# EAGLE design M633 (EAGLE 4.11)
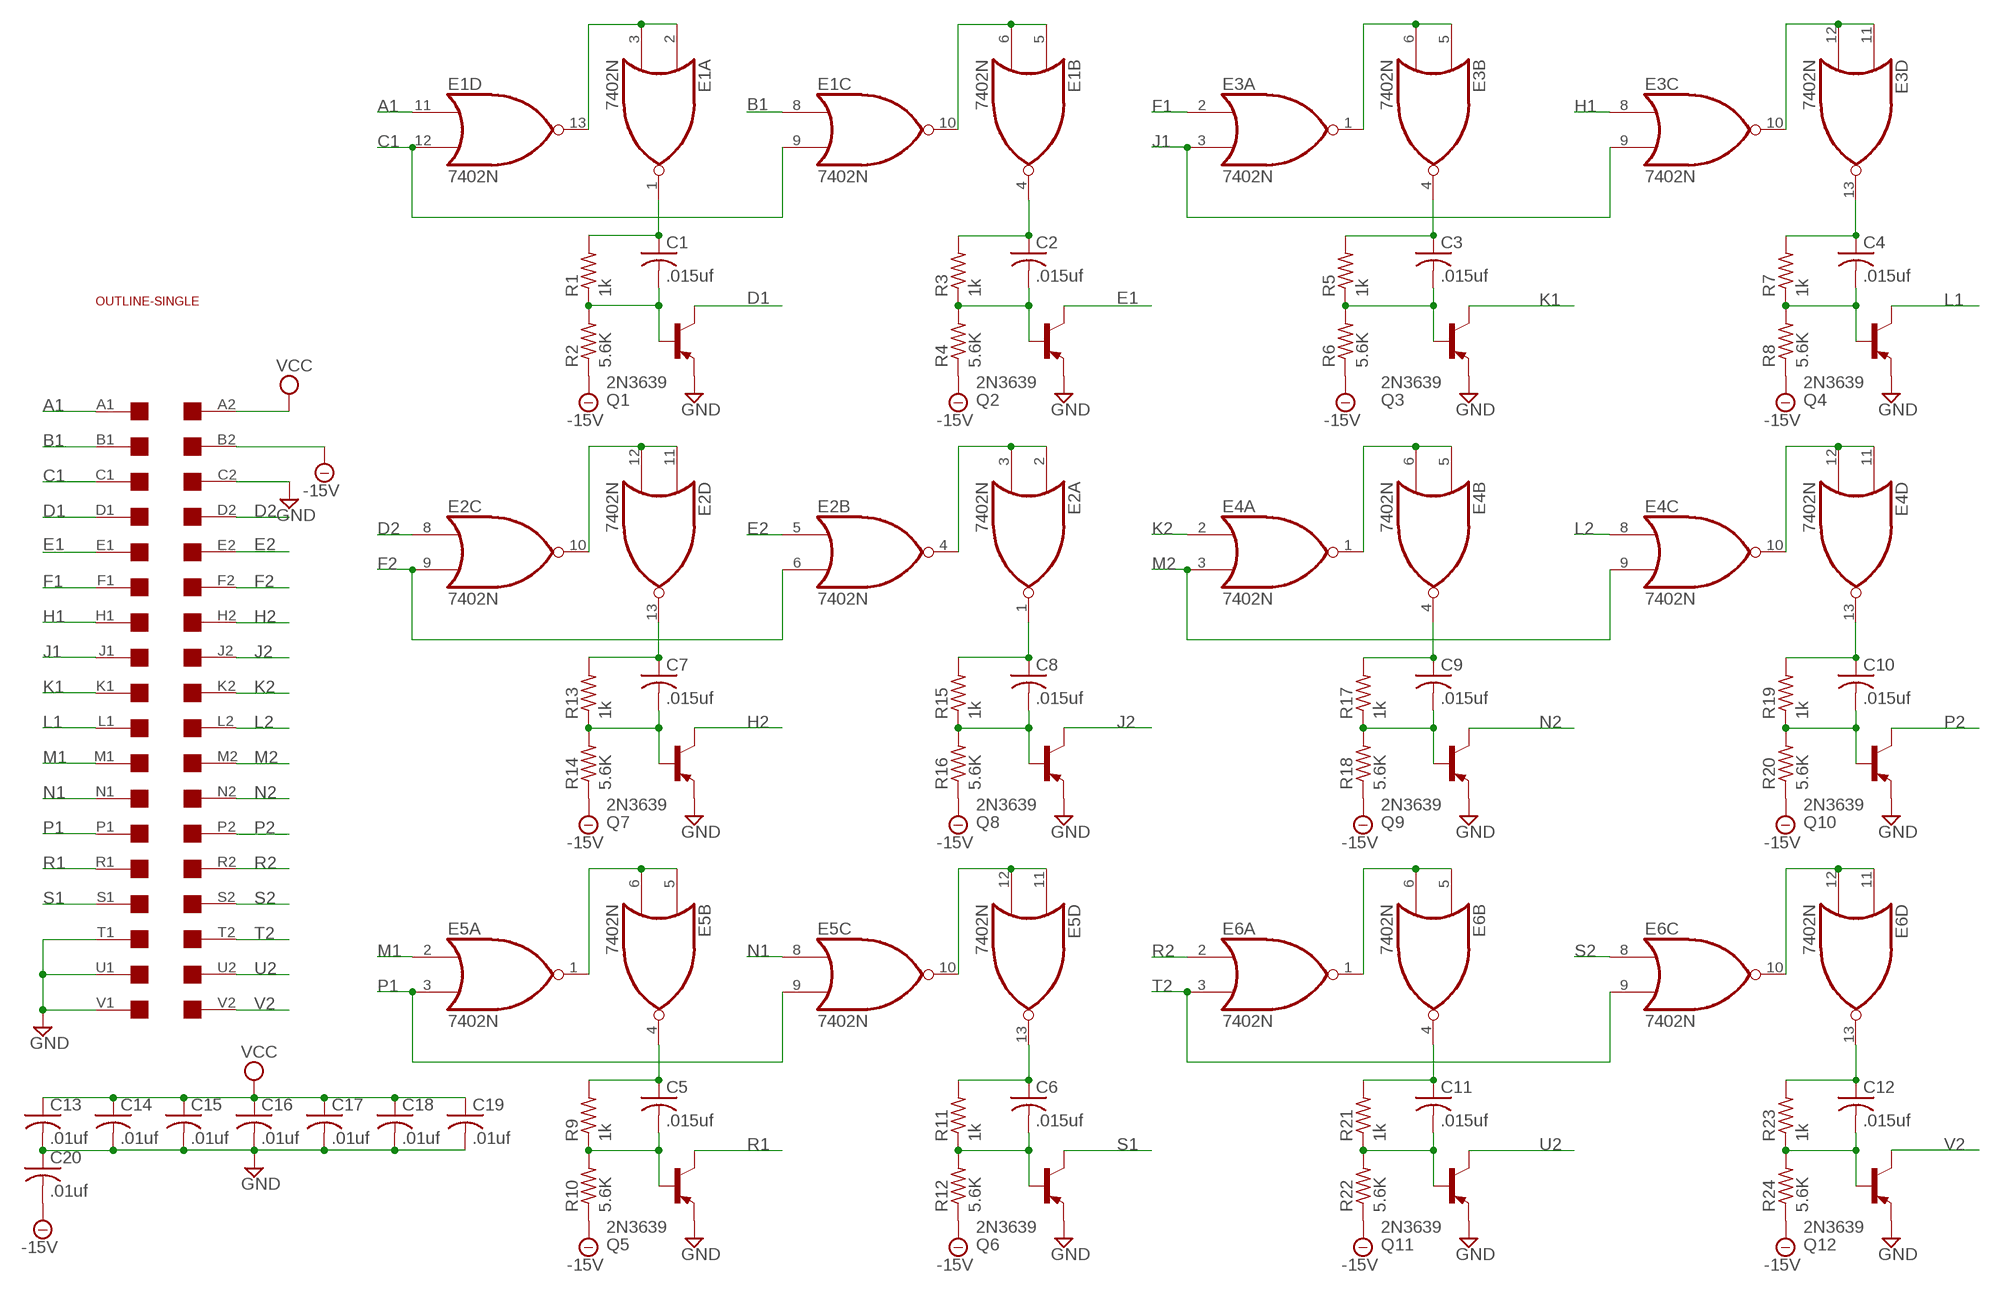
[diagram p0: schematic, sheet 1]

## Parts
C1  .015uf  C-US050-025X075  [C050-025X075]
C2  .015uf  C-US050-025X075  [C050-025X075]
C3  .015uf  C-US050-025X075  [C050-025X075]
C4  .015uf  C-US050-025X075  [C050-025X075]
C5  .015uf  C-US050-025X075  [C050-025X075]
C6  .015uf  C-US050-025X075  [C050-025X075]
C7  .015uf  C-US050-025X075  [C050-025X075]
C8  .015uf  C-US050-025X075  [C050-025X075]
C9  .015uf  C-US050-025X075  [C050-025X075]
C10  .015uf  C-US050-025X075  [C050-025X075]
C11  .015uf  C-US050-025X075  [C050-025X075]
C12  .015uf  C-US050-025X075  [C050-025X075]
C13  .01uf  C-US050-025X075  [C050-025X075]
C14  .01uf  C-US050-025X075  [C050-025X075]
C15  .01uf  C-US050-025X075  [C050-025X075]
C16  .01uf  C-US050-025X075  [C050-025X075]
C17  .01uf  C-US050-025X075  [C050-025X075]
C18  .01uf  C-US050-025X075  [C050-025X075]
C19  .01uf  C-US050-025X075  [C050-025X075]
C20  .01uf  C-US050-025X075  [C050-025X075]
E1  7402N  [DIL14]
E2  7402N  [DIL14]
E3  7402N  [DIL14]
E4  7402N  [DIL14]
E5  7402N  [DIL14]
E6  7402N  [DIL14]
Q1  2N3639  2N5415  [TO39]
Q2  2N3639  2N5415  [TO39]
Q3  2N3639  2N5415  [TO39]
Q4  2N3639  2N5415  [TO39]
Q5  2N3639  2N5415  [TO39]
Q6  2N3639  2N5415  [TO39]
Q7  2N3639  2N5415  [TO39]
Q8  2N3639  2N5415  [TO39]
Q9  2N3639  2N5415  [TO39]
Q10  2N3639  2N5415  [TO39]
Q11  2N3639  2N5415  [TO39]
Q12  2N3639  2N5415  [TO39]
R1  1k  R-US_0207/10  [0207/10]
R2  5.6K  R-US_0207/10  [0207/10]
R3  1k  R-US_0207/10  [0207/10]
R4  5.6K  R-US_0207/10  [0207/10]
R5  1k  R-US_0207/10  [0207/10]
R6  5.6K  R-US_0207/10  [0207/10]
R7  1k  R-US_0207/10  [0207/10]
R8  5.6K  R-US_0207/10  [0207/10]
R9  1k  R-US_0207/10  [0207/10]
R10  5.6K  R-US_0207/10  [0207/10]
R11  1k  R-US_0207/10  [0207/10]
R12  5.6K  R-US_0207/10  [0207/10]
R13  1k  R-US_0207/10  [0207/10]
R14  5.6K  R-US_0207/10  [0207/10]
R15  1k  R-US_0207/10  [0207/10]
R16  5.6K  R-US_0207/10  [0207/10]
R17  1k  R-US_0207/10  [0207/10]
R18  5.6K  R-US_0207/10  [0207/10]
R19  1k  R-US_0207/10  [0207/10]
R20  5.6K  R-US_0207/10  [0207/10]
R21  1k  R-US_0207/10  [0207/10]
R22  5.6K  R-US_0207/10  [0207/10]
R23  1k  R-US_0207/10  [0207/10]
R24  5.6K  R-US_0207/10  [0207/10]
U$1  SINGLE  [EDGE-CON2]
U$2  OUTLINE-SINGLE  [SINGLE]

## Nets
-15V: C20.2 R2.1 R4.1 R6.1 R8.1 R10.1 R12.1 R14.1 R16.1 R18.1 R20.1 R22.1 R24.1 U$1.B2
A1: E1.11(D:I0) U$1.A1
B1: E1.8(C:I0) U$1.B1
C1: E1.9(C:I1) E1.12(D:I1) U$1.C1
D1: Q1.3(C) U$1.D1
D2: E2.8(C:I0) U$1.D2
E1: Q2.3(C) U$1.E1
E2: E2.5(B:I0) U$1.E2
F1: E3.2(A:I0) U$1.F1
F2: E2.6(B:I1) E2.9(C:I1) U$1.F2
GND: C13.2 C14.2 C15.2 C16.2 C17.2 C18.2 C19.2 C20.1 Q1.1(E) Q2.1(E) Q3.1(E) Q4.1(E) Q5.1(E) Q6.1(E) Q7.1(E) Q8.1(E) Q9.1(E) Q10.1(E) Q11.1(E) Q12.1(E) U$1.C2 U$1.T1 U$1.U1 U$1.V1
H1: E3.8(C:I0) U$1.H1
H2: Q7.3(C) U$1.H2
J1: E3.3(A:I1) E3.9(C:I1) U$1.J1
J2: Q8.3(C) U$1.J2
K1: Q3.3(C) U$1.K1
K2: E4.2(A:I0) U$1.K2
L1: Q4.3(C) U$1.L1
L2: E4.8(C:I0) U$1.L2
M1: E5.2(A:I0) U$1.M1
M2: E4.3(A:I1) E4.9(C:I1) U$1.M2
N1: E5.8(C:I0) U$1.N1
N2: Q9.3(C) U$1.N2
N$1: E1.2(A:I0) E1.3(A:I1) E1.13(D:O)
N$2: C1.1 E1.1(A:O) R1.2
N$3: C1.2 Q1.2(B) R1.1 R2.2
N$4: C3.1 E3.4(B:O) R5.2
N$5: C2.1 E1.4(B:O) R3.2
N$6: C2.2 Q2.2(B) R3.1 R4.2
N$7: E1.5(B:I0) E1.6(B:I1) E1.10(C:O)
N$8: E2.10(C:O) E2.11(D:I0) E2.12(D:I1)
N$9: E2.2(A:I0) E2.3(A:I1) E2.4(B:O)
N$10: E4.1(A:O) E4.5(B:I0) E4.6(B:I1)
N$11: E4.10(C:O) E4.11(D:I0) E4.12(D:I1)
N$12: E6.10(C:O) E6.11(D:I0) E6.12(D:I1)
N$13: E6.1(A:O) E6.5(B:I0) E6.6(B:I1)
N$14: E5.10(C:O) E5.11(D:I0) E5.12(D:I1)
N$15: E5.1(A:O) E5.5(B:I0) E5.6(B:I1)
N$16: E3.10(C:O) E3.11(D:I0) E3.12(D:I1)
N$17: E3.1(A:O) E3.5(B:I0) E3.6(B:I1)
N$18: C4.1 E3.13(D:O) R7.2
N$19: C9.1 E4.4(B:O) R17.2
N$20: C10.1 E4.13(D:O) R19.2
N$21: C8.1 E2.1(A:O) R15.2
N$22: C7.1 E2.13(D:O) R13.2
N$23: C7.2 Q7.2(B) R13.1 R14.2
N$24: C8.2 Q8.2(B) R15.1 R16.2
N$25: C9.2 Q9.2(B) R17.1 R18.2
N$26: C10.2 Q10.2(B) R19.1 R20.2
N$27: C5.1 E5.4(B:O) R9.2
N$28: C5.2 Q5.2(B) R9.1 R10.2
N$29: C6.2 Q6.2(B) R11.1 R12.2
N$30: C11.2 Q11.2(B) R21.1 R22.2
N$31: C12.2 Q12.2(B) R23.1 R24.2
N$32: C6.1 E5.13(D:O) R11.2
N$33: C11.1 E6.4(B:O) R21.2
N$34: C12.1 E6.13(D:O) R23.2
N$35: C3.2 Q3.2(B) R5.1 R6.2
N$36: C4.2 Q4.2(B) R7.1 R8.2
P1: E5.3(A:I1) E5.9(C:I1) U$1.P1
P2: Q10.3(C) U$1.P2
R1: Q5.3(C) U$1.R1
R2: E6.2(A:I0) U$1.R2
S1: Q6.3(C) U$1.S1
S2: E6.8(C:I0) U$1.S2
T2: E6.3(A:I1) E6.9(C:I1) U$1.T2
U2: Q11.3(C) U$1.U2
V2: Q12.3(C) U$1.V2
VCC: C13.1 C14.1 C15.1 C16.1 C17.1 C18.1 C19.1 U$1.A2

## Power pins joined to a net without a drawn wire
GND: E1.7(P:GND) E2.7(P:GND) E3.7(P:GND) E4.7(P:GND) E5.7(P:GND) E6.7(P:GND)
VCC: E1.14(P:VCC) E2.14(P:VCC) E3.14(P:VCC) E4.14(P:VCC) E5.14(P:VCC) E6.14(P:VCC)

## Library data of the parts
C1-C20 = rcl:C-US: CAPACITOR, American symbol
E1-E6 = 74xx-us:74*02: Quad 2-input NOR gate
Q1-Q12 = transistor-pnp:2N5415*: PNP Transistror
R1-R24 = rcl:R-US_: RESISTOR, American symbol
U$1 = dec-con:SINGLE: Single-Height DEC board
U$2 = dec-con:OUTLINE-*: Board outlines for DEC boards.

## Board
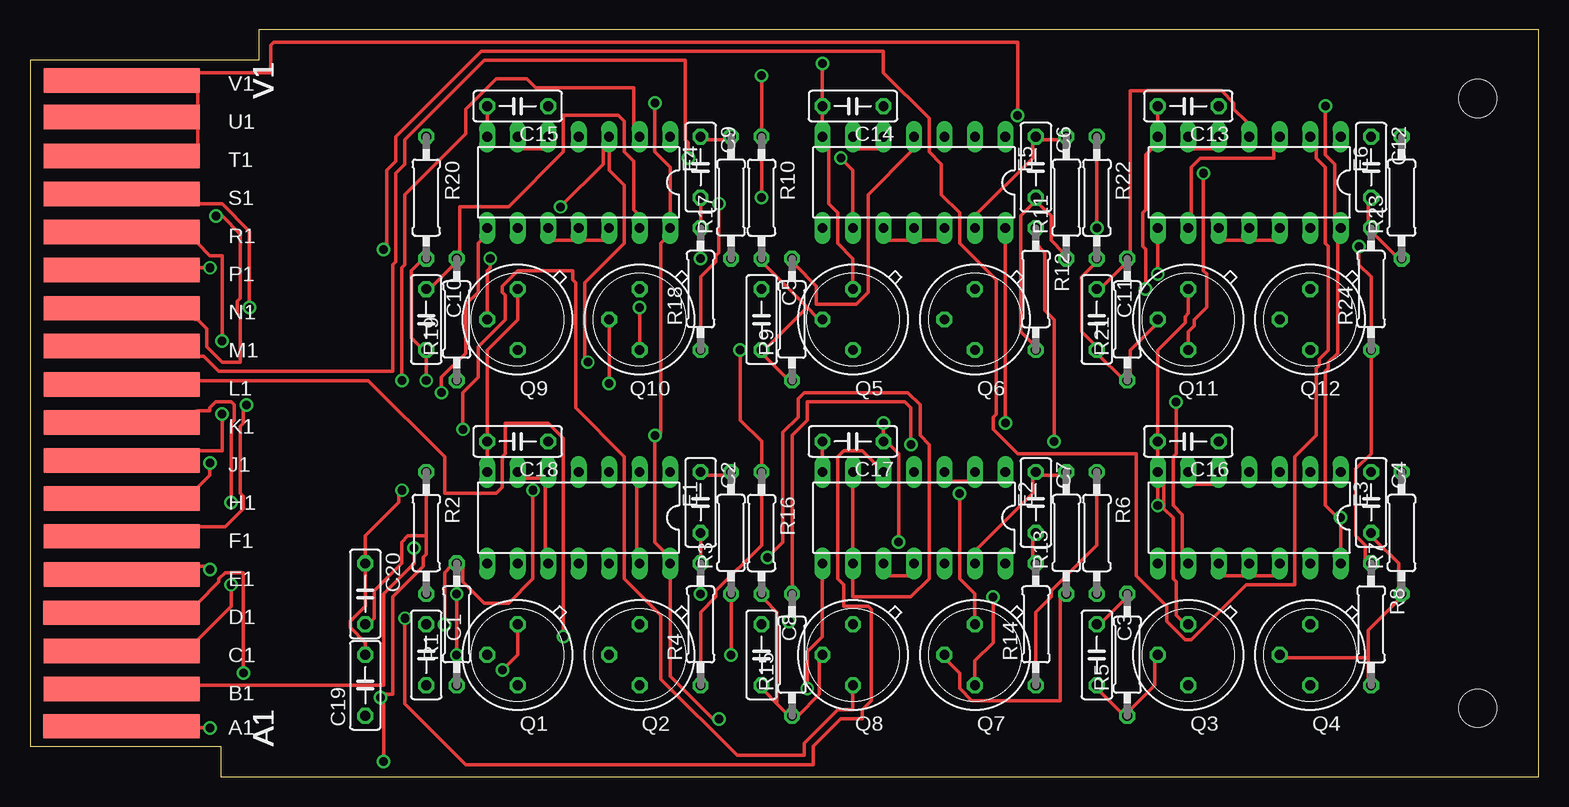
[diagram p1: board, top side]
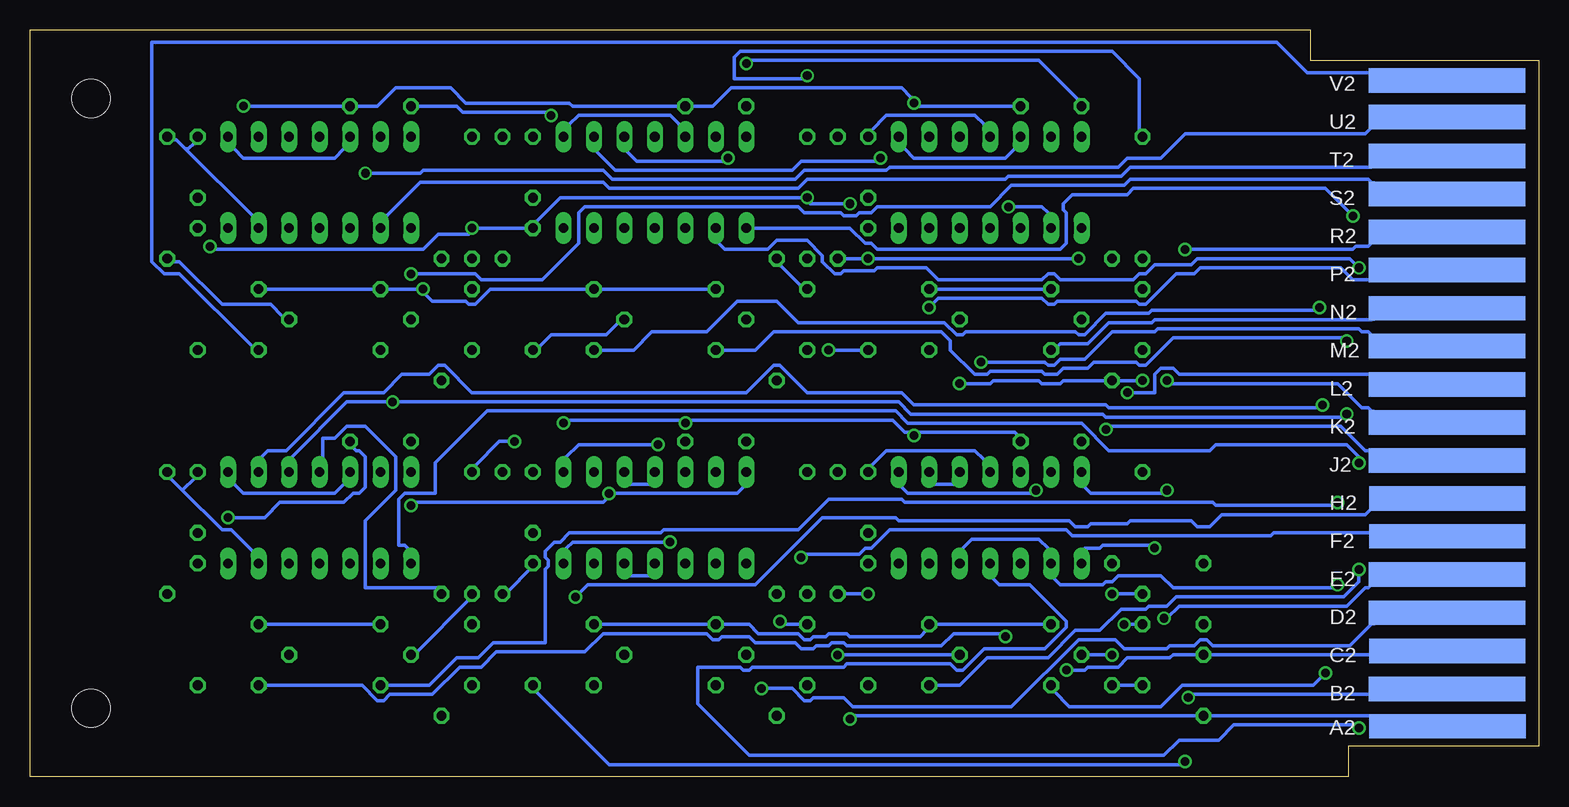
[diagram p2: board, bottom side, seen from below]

Size 125.73 x 62.23 mm. Coordinates in mm from the lower left corner, seen from the top.
Copper layers (1*16): Top 0.035mm / dielectric 1.5mm / Bottom 0.035mm
Design rules "10mils": minimum track width 12mil, minimum drill 28mil, track to track 10mil, track to pad 10mil, pad to pad 10mil, via to via 10mil, smd to smd 10mil, copper to edge 25mil, drill to drill 10mil, minimum pad ring 10mil, minimum via ring 8mil, stop-mask expansion 0mil, vias tented up to drill 0mil, thermal gap 10mil

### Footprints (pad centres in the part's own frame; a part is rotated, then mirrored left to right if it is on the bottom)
C050-025X075 = drill 0.813 octagon: 1 -2.54,0; 2 2.54,0
DIL14 = drill 0.813 long: 1 -7.62,-3.81; 2 -5.08,-3.81; 3 -2.54,-3.81; 4 0,-3.81; 5 2.54,-3.81; 6 5.08,-3.81; 7 7.62,-3.81; 8 7.62,3.81; 9 5.08,3.81; 10 2.54,3.81; 11 0,3.81; 12 -2.54,3.81; 13 -5.08,3.81; 14 -7.62,3.81
TO39 = drill 0.813 octagon: 1 0,-2.54; 2 2.54,0; 3 0,2.54
0207/10 = drill 0.813 octagon: 1 -5.08,0; 2 5.08,0
EDGE-CON2 = smd 13.017 x 2.032: A1 7.633,4.207; B1 7.639,7.327; C1 7.636,10.489; D1 7.633,13.665; E1 7.642,16.84; F1 7.642,20.041; H1 7.642,23.19; J1 7.642,26.34; K1 7.642,29.515; L1 7.642,32.69; M1 7.642,35.89; N1 7.642,39.04; P1 7.642,42.24; R1 7.642,45.39; S1 7.642,48.565; T1 7.642,51.74; U1 7.642,54.966; V1 7.642,58.026 | smd 13.017 x 2.032 bottom: A2 7.614,4.207; B2 7.642,7.328; C2 7.617,10.49; D2 7.642,13.665; E2 7.642,16.84; F2 7.617,20.041; H2 7.617,23.19; J2 7.642,26.34; K2 7.642,29.515; L2 7.642,32.69; M2 7.642,35.89; N2 7.642,39.04; P2 7.642,42.24; R2 7.642,45.39; S2 7.642,48.565; T2 7.642,51.74; U2 7.642,54.966; V2 7.642,58.026
SINGLE = hole 3.175: 120.65,56.515; 120.65,5.715

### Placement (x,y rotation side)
C1  33.02,10.16 270 top
C2  55.88,22.86 270 top
C3  88.9,10.16 270 top
C4  111.76,22.86 270 top
C5  60.96,38.1 270 top
C6  83.82,50.8 270 top
C7  83.82,22.86 270 top
C8  60.96,10.16 270 top
C9  55.88,50.8 270 top
C10  33.02,38.1 270 top
C11  88.9,38.1 270 top
C12  111.76,50.8 270 top
C13  96.52,55.88 180 top
C14  68.58,55.88 180 top
C15  40.64,55.88 180 top
C16  96.52,27.94 180 top
C17  68.58,27.94 180 top
C18  40.64,27.94 180 top
C19  27.94,7.62 90 top
C20  27.94,15.24 270 top
E1  45.72,21.59 180 top
E2  73.66,21.59 180 top
E3  101.6,21.59 180 top
E4  45.72,49.53 180 top
E5  73.66,49.53 180 top
E6  101.6,49.53 180 top
Q1  40.64,10.16 180 top
Q2  50.8,10.16 180 top
Q3  96.52,10.16 180 top
Q4  106.68,10.16 180 top
Q5  68.58,38.1 180 top
Q6  78.74,38.1 180 top
Q7  78.74,10.16 180 top
Q8  68.58,10.16 180 top
Q9  40.64,38.1 180 top
Q10  50.8,38.1 180 top
Q11  96.52,38.1 180 top
Q12  106.68,38.1 180 top
R1  35.56,12.7 90 top
R2  33.02,20.32 270 top
R3  58.42,20.32 90 top
R4  55.88,12.7 90 top
R5  91.44,10.16 90 top
R6  88.9,20.32 270 top
R7  114.3,20.32 90 top
R8  111.76,12.7 270 top
R9  63.5,38.1 90 top
R10  60.96,48.26 270 top
R11  86.36,48.26 90 top
R12  83.82,40.64 270 top
R13  86.36,20.32 90 top
R14  83.82,12.7 90 top
R15  63.5,10.16 90 top
R16  60.96,20.32 270 top
R17  58.42,48.26 90 top
R18  55.88,40.64 90 top
R19  35.56,38.1 90 top
R20  33.02,48.26 270 top
R21  91.44,38.1 90 top
R22  88.9,48.26 270 top
R23  114.3,48.26 90 top
R24  111.76,40.64 90 top
U$1  0,0 0 top
U$2  0,0 0 top

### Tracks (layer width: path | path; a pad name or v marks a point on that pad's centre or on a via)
-15V  (via drill 0.71)
  Top 0.305: 33.02,20.07 33.02,24.89 R2.1 | 33.02,20.07 33.02,18.54 32.77,18.29 32.77,17.53 30.23,14.99 30.23,6.86 29.46,6.86 v29.21,6.6 29.46,6.1 v29.46,1.27 | 33.02,20.07 31.5,20.07 30.99,19.56 30.99,17.78 28.7,15.49 28.7,13.21 28.45,12.95 C20.2 | R4.1 55.88,8.13 55.88,13.72 57.15,14.99 57.15,15.49 60.96,19.3 60.96,24.89 R16.1 60.96,25.91 60.96,27.94 59.18,29.72 v59.18,35.56 | R14.1 83.82,8.13 83.82,13.72 85.09,14.99 85.09,15.49 88.9,19.3 88.9,24.89 R6.1 | R8.1 111.25,18.03 111.25,19.3 110.49,20.07 110.49,25.65 111.76,26.92 111.76,35.05 R24.1 111.76,36.07 111.76,41.66 110.74,42.67 v110.74,44.2 | v88.9,45.72 88.9,52.83 R22.1 | v60.96,58.42 60.96,53.85 R10.1 60.96,52.83 v60.96,48.26 | v85.34,27.94 85.34,38.1 84.58,38.86 84.58,43.69 83.82,44.45 83.82,45.21 R12.1 | v57.4,47.75 57.4,43.69 57.15,43.43 57.15,42.93 55.88,41.66 55.88,36.07 R18.1
  Bottom 0.305: v29.21,6.6 28.96,6.86 13.97,6.86 U$1.B2 | v59.18,35.56 56.39,35.56 R18.1 | v60.96,58.42 61.21,58.17 67.06,58.17 67.06,59.94 66.55,60.45 35.56,60.45 33.27,58.17 33.27,53.85 R20.1 | v110.74,44.2 110.49,43.94 92.96,43.94 91.69,45.21 89.15,45.21 v88.9,45.72 84.33,45.72 R12.1 83.57,46.23 81.53,48.26 v60.96,48.26 60.71,47.75 v57.4,47.75 | v85.34,27.94 86.61,27.94 88.65,25.91 R6.1 | v29.46,1.27 29.72,1.02 77.47,1.02 83.57,7.11 R14.1
A1  (via drill 0.71)
  Top 0.305: v14.99,4.06 13.97,4.06 U$1.A1
  Bottom 0.305: v14.99,4.06 15.24,4.32 25.4,4.32 26.67,3.05 29.97,3.05 31.24,1.78 65.79,1.78 70.1,6.1 70.1,9.14 66.55,9.14 66.29,8.89 65.79,8.89 65.53,9.14 57.91,9.14 57.66,9.4 49.02,9.4 48.51,8.89 48.01,8.89 46.23,10.67 41.15,10.67 39.37,12.45 39.37,12.95 42.42,16 44.96,16 45.47,16.51 E1.11
B1  (via drill 0.71)
  Top 0.305: v32,19.05 32,17.78 29.46,15.24 29.46,7.62 13.97,7.62 U$1.B1
  Bottom 0.305: v32,19.05 32.26,19.3 36.32,19.3 36.58,19.05 37.85,19.05 E1.8
C1  (via drill 0.71)
  Top 0.305: v16.76,16 16.76,14.22 13.97,11.43 U$1.C1
  Bottom 0.305: v16.76,16 17.02,15.75 30.48,15.75 31.5,16.76 35.05,16.76 35.56,16.26 36.07,16.26 36.32,16 39.88,16 40.39,16.51 E1.9 40.89,19.05 41.66,19.81 47.24,19.81 48.01,19.05 E1.12
D1  (via drill 0.71)
  Top 0.305: v17.78,8.64 17.78,17.02 16.26,17.02 15.75,16.51 15.75,16.26 13.97,14.48 U$1.D1
  Bottom 0.305: v17.78,8.64 18.8,7.62 29.72,7.62 31.5,5.84 39.12,5.84 40.39,7.11 Q1.3
D2  (via drill 0.71)
  Top 0.305: v64.77,7.37 64.77,10.41 66.04,11.68 66.04,16.51 E2.8
  Bottom 0.305: v64.77,7.37 62.23,7.37 61.21,6.35 60.71,6.35 60.45,6.6 57.91,6.6 57.15,5.84 43.94,5.84 38.35,11.43 35.31,11.43 34.54,10.67 30.99,10.67 30.73,10.92 28.7,10.92 28.19,11.43 27.69,11.43 27.18,10.92 15.75,10.92 13.97,12.7 U$1.D2
E1  (via drill 0.71)
  Top 0.305: v14.99,17.27 14.99,17.53 13.97,17.53 U$1.E1
  Bottom 0.305: v14.99,17.27 14.99,16.26 16.26,14.99 30.23,14.99 30.99,14.22 32.51,14.22 32.77,13.97 34.8,13.97 36.58,12.19 38.61,12.19 40.89,9.91 45.97,9.91 48.26,7.62 50.29,7.62 Q2.3
E2  (via drill 0.71)
  Top 0.305: v31.24,13.21 31.24,6.1 36.32,1.02 65.28,1.02 65.28,2.54 67.56,4.83 69.34,4.83 69.34,5.59 70.1,6.35 70.1,13.97 69.85,14.22 67.82,14.22 67.82,16 67.31,16.51 67.31,26.67 67.82,27.18 69.34,27.18 70.61,25.91 E2.5
  Bottom 0.305: v31.24,13.21 30.99,13.21 29.97,14.22 16,14.22 14.48,15.75 14.22,15.75 13.97,16 U$1.E2
F1  (via drill 0.71)
  Top 0.305: v18.03,30.99 17.78,30.73 17.78,29.46 17.53,29.21 17.53,23.62 17.78,23.37 17.78,22.35 16.26,20.83 13.97,20.83 U$1.F1
  Bottom 0.305: v18.03,30.99 18.29,30.73 35.81,30.73 36.07,30.99 52.07,30.99 53.09,32 60.96,32 63.25,34.29 63.75,34.29 66.04,32 88.9,32 91.19,34.29 91.69,34.29 92.46,33.53 94.74,33.53 96.27,32 99.57,32 104.39,27.18 105.92,27.18 106.43,26.67 E3.2
F2  (via drill 0.71)
  Top 0.305: v61.47,18.29 62.74,19.56 62.74,28.7 64.01,29.97 64.01,31.5 64.52,32 73.15,32 74.17,30.99 74.17,28.45 74.93,27.69 74.93,16.51 73.41,14.99 68.58,14.99 68.58,16.51 E2.9 68.58,19.05 68.58,24.13 E2.6
  Bottom 0.305: v61.47,18.29 61.21,18.54 56.64,18.54 56.13,19.05 55.63,19.05 54.1,20.57 39.37,20.57 38.86,20.07 22.35,20.07 22.1,20.32 13.97,20.32 U$1.F2
GND  (via drill 0.71)
  Top 0.305: E1.7 38.1,26.67 38.1,27.43 C18.2 38.1,28.45 38.1,35.56 40.64,38.1 40.64,40.13 Q9.1 | C19.2 27.94,10.67 27.94,11.18 26.67,12.45 26.67,12.95 27.94,14.22 27.94,17.27 C20.1 27.94,18.29 27.94,20.07 30.73,22.86 30.73,23.62 v30.99,23.88 | E2.7 66.04,26.67 66.04,27.43 C17.2 | v77.47,23.62 77.47,16.51 78.74,15.24 78.74,13.21 Q7.1 | U$1.T1 13.97,52.58 13.97,54.1 U$1.U1 13.97,55.88 13.97,57.15 U$1.V1 13.97,58.67 20.07,58.67 20.07,60.96 20.32,61.21 82.3,61.21 v82.3,55.12 | E4.7 38.1,54.61 38.1,55.37 C15.2 | v66.04,59.44 66.04,56.39 C14.2 66.04,55.37 66.04,54.61 E5.7 66.55,52.32 66.55,47.75 67.31,46.99 67.31,44.45 68.58,43.18 68.58,41.15 Q5.1 | C13.2 93.98,55.37 93.98,54.61 E6.7 93.47,52.32 92.96,51.82 92.96,47.24 92.71,46.99 92.71,44.2 92.96,43.94 v92.96,40.64 | E3.7 93.98,26.67 93.98,27.43 C16.2 93.98,28.45 93.98,35.56 96.27,37.85 96.27,38.35 96.52,38.61 96.52,40.13 Q11.1 | Q3.1 96.01,12.95 95.5,13.46 95.5,16.26 95.25,16.51 95.25,21.59 94.49,22.35 94.49,24.38 E3.7 | v93.98,22.61 93.98,24.13 E3.7 | v39.37,8.89 40.64,10.16 40.64,12.19 Q1.1
  Bottom 0.305: Q9.1 41.15,40.64 50.29,40.64 Q10.1 | U$1.C2 13.97,10.16 27.43,10.16 C19.2 28.45,10.16 30.48,10.16 30.73,9.91 34.29,9.91 35.05,9.14 37.59,9.14 37.85,8.89 v39.37,8.89 | v30.99,23.88 31.24,23.62 37.34,23.62 37.85,24.13 E1.7 | Q1.1 41.15,12.7 50.29,12.7 Q2.1 51.05,12.19 51.56,11.68 57.4,11.68 57.66,11.94 59.18,11.94 59.44,11.68 60.45,11.68 60.71,11.43 61.21,11.43 61.72,11.94 65.02,11.94 65.79,12.7 68.07,12.7 Q8.1 69.09,12.7 78.23,12.7 Q7.1 | E2.7 66.29,24.13 66.8,23.62 v77.47,23.62 77.72,23.11 77.98,22.86 93.73,22.86 v93.98,22.61 | v66.04,59.44 65.79,59.69 41.66,59.69 38.35,56.39 C15.2 | Q5.1 69.09,40.64 78.23,40.64 Q6.1 79.25,40.64 87.38,40.64 88.65,39.37 89.15,39.37 89.41,39.62 92.2,39.62 92.71,40.13 v92.96,40.64 96.01,40.64 Q11.1 97.03,40.64 106.17,40.64 Q12.1 | Q3.1 97.03,12.7 106.17,12.7 Q4.1 | v82.3,55.12 82.55,55.37 89.66,55.37 90.17,55.88 93.47,55.88 C13.2
H1  (via drill 0.71)
  Top 0.305: v14.99,26.16 14.99,25.15 13.97,24.13 U$1.H1
  Bottom 0.305: v14.99,26.16 14.99,26.67 16,27.69 26.92,27.69 27.43,27.18 35.81,27.18 38.1,29.46 52.58,29.46 53.59,30.48 87.63,30.48 91.95,26.16 91.95,23.62 94.49,23.62 95,23.11 95,19.3 94.49,19.3 94.23,19.05 E3.8
H2  (via drill 0.71)
  Top 0.305: v80.26,14.99 80.26,11.18 78.74,9.65 78.74,8.13 Q7.3
  Bottom 0.305: v80.26,14.99 79.25,16 65.28,16 59.69,21.59 53.59,21.59 53.34,21.34 39.12,21.34 38.61,20.83 37.59,20.83 37.34,21.08 34.29,21.08 34.04,21.34 28.96,21.34 28.45,20.83 27.43,20.83 26.42,21.84 14.48,21.84 13.97,22.35 U$1.H2
J1  (via drill 0.71)
  Top 0.305: v16,30.23 16,27.18 13.97,27.18 U$1.J1 | v95.5,31.24 95.5,26.92 95.25,26.67 95.25,22.61 96.01,21.84 96.01,18.8 E3.9
  Bottom 0.305: v16,30.23 16.26,29.97 36.07,29.97 36.32,30.23 52.32,30.23 53.34,31.24 v95.5,31.24 99.31,31.24 103.89,26.67 E3.3
J2  (via drill 0.71)
  Top 0.305: v36.07,28.96 36.07,32 37.34,33.27 37.34,35.81 39.62,38.1 39.62,40.13 39.37,40.39 39.37,40.89 40.64,42.16 45.21,42.16 45.21,41.4 45.47,41.15 45.47,30.73 49.53,26.67 49.53,16.51 52.58,13.46 52.58,8.13 58.93,1.78 64.52,1.78 64.52,2.79 67.31,5.59 68.58,5.59 68.58,7.11 Q8.3
  Bottom 0.305: v36.07,28.96 35.81,29.21 16.51,29.21 14.48,27.18 13.97,27.18 U$1.J2
K1  (via drill 0.71)
  Top 0.305: v16.76,22.86 16.76,29.46 17.02,29.72 17.02,30.99 16.76,31.24 15.49,31.24 14.99,30.73 14.99,30.48 13.97,30.48 U$1.K1
  Bottom 0.305: v16.76,22.86 17.02,22.61 26.92,22.61 27.18,22.86 52.83,22.86 53.09,23.11 59.18,23.11 61.72,20.57 72.9,20.57 73.15,20.32 80.77,20.32 81.53,19.56 82.04,19.56 82.8,18.8 82.8,18.29 82.55,18.03 82.55,17.53 82.8,17.27 82.8,11.18 87.12,11.18 88.39,9.91 90.17,9.91 92.46,7.62 96.01,7.62 Q3.3
K2  (via drill 0.71)
  Top 0.305: v30.99,33.02 30.99,42.42 31.24,42.67 31.24,48.51 36.32,53.59 36.32,55.63 38.86,58.17 41.4,58.17 42.16,57.4 50.29,57.4 50.29,54.36 E4.2
  Bottom 0.305: v30.99,33.02 30.73,32.77 16.76,32.77 14.73,30.73 14.22,30.73 13.97,30.48 U$1.K2
L1  (via drill 0.71)
  Top 0.305: v44.45,11.68 44.45,28.19 43.18,29.46 39.62,29.46 39.62,26.92 39.37,26.67 39.37,24.13 38.86,23.62 34.54,23.62 34.54,26.67 28.19,33.02 13.97,33.02 U$1.L1
  Bottom 0.305: v44.45,11.68 44.7,11.94 48.77,11.94 49.78,10.92 57.66,10.92 57.91,11.18 58.93,11.18 59.18,10.92 60.2,10.92 60.45,10.67 61.47,10.67 61.98,11.18 65.28,11.18 65.79,11.68 68.07,11.68 68.33,11.43 68.83,11.43 69.34,11.94 77.98,11.94 79.5,10.41 86.87,10.41 88.14,9.14 89.92,9.14 92.2,6.86 95.76,6.86 96.27,6.35 96.77,6.35 98.04,7.62 106.17,7.62 Q4.3
L2  (via drill 0.71)
  Top 0.305: v34.29,32 34.29,33.27 36.32,35.31 36.32,39.37 37.34,40.39 37.34,44.45 37.59,44.7 E4.8
  Bottom 0.305: v34.29,32 32,32 32,33.53 31.5,34.04 30.48,34.04 29.97,33.53 13.97,33.53 U$1.L2
M1  (via drill 0.71)
  Top 0.305: v54.86,51.56 54.86,52.83 54.61,53.09 54.61,59.69 37.85,59.69 31.24,53.09 31.24,51.05 30.48,50.29 30.48,42.93 30.23,42.67 30.23,33.78 15.75,33.78 14.48,35.05 13.97,35.05 U$1.M1
  Bottom 0.305: v54.86,51.56 55.12,51.31 61.47,51.31 62.23,50.55 76.96,50.55 78.49,52.07 E5.2
M2  (via drill 0.71)
  Top 0.305: v46.48,34.54 46.23,34.8 46.23,41.15 49.53,44.45 49.53,49.28 48.26,50.55 48.26,52.07 E4.3 47.75,52.32 47.75,51.05 v44.2,47.5
  Bottom 0.305: v46.48,34.54 41.15,34.54 40.89,34.29 40.39,34.29 39.88,34.8 37.85,34.8 35.56,37.08 32,37.08 31.75,37.34 14.99,37.34 14.73,37.08 14.22,37.08 13.97,36.83 U$1.M2 | v44.2,47.5 41.4,47.5 40.89,46.99 E4.9
N1  (via drill 0.71)
  Top 0.305: v15.49,46.74 16,46.74 17.53,45.21 17.53,39.88 17.27,39.62 17.27,38.61 17.53,38.35 17.53,34.54 16,34.54 14.73,35.81 14.73,37.34 13.97,38.1 U$1.N1
  Bottom 0.305: v15.49,46.74 17.78,49.02 33.78,49.02 34.29,48.51 38.86,48.51 39.62,47.75 39.62,47.24 39.37,46.99 39.37,44.45 39.88,43.94 55.12,43.94 55.63,44.45 56.13,44.45 57.4,45.72 65.53,45.72 E5.8
N2
  Bottom 0.305: Q9.3 40.13,35.81 39.88,36.07 37.59,36.07 35.81,37.85 32.26,37.85 32,38.1 13.97,38.1 U$1.N2
N$1
  Top 0.305: E1.13 50.55,19.05 50.55,24.13 E1.2
  Bottom 0.305: E1.3 48.77,24.38 50.29,24.38 E1.2
N$2  (via drill 0.71)
  Top 0.305: v34.54,12.7 34.54,17.02 35.05,17.53 R1.2 36.07,17.53 36.07,16.26 37.85,14.48 39.88,14.48 41.91,16.51 v41.91,23.88
  Bottom 0.305: v34.54,12.7 33.53,12.7 C1.1 | v41.91,23.88 42.16,23.62 52.58,23.62 53.09,24.13 E1.1
N$3  (via drill 0.71)
  Top 0.305: v35.56,15.24 v35.56,10.16 35.56,8.13 R1.1
  Bottom 0.305: C1.2 33.53,7.62 35.05,7.62 R1.1 | v35.56,15.24 33.53,15.24 R2.2 | v35.56,10.16 37.59,10.16 Q1.2
N$4
  Top 0.305: C3.1 89.41,12.95 91.19,14.73 R5.2
  Bottom 0.305: E3.4 101.35,26.67 101.35,28.19 100.33,28.19 99.31,29.21 97.79,29.21 95.25,26.67 95.25,23.88 97.79,21.34 97.79,15.75 91.69,15.75 R5.2
N$5
  Top 0.305: R3.2 57.91,25.15 56.39,25.15 C2.1
  Bottom 0.305: E1.4 46.23,26.42 46.99,27.18 54.36,27.18 55.63,25.91 C2.1
N$6  (via drill 0.71)
  Top 0.305: C2.2 55.88,19.81 55.88,18.29 R4.2 55.88,17.27 v55.88,15.24 | v58.42,10.16 58.42,14.73 R3.1
  Bottom 0.305: v58.42,10.16 48.77,10.16 Q2.2 | v55.88,15.24 57.91,15.24 R3.1
N$7
  Top 0.305: E1.6 41.15,24.89 42.67,24.89 E1.5 42.93,24.13 42.93,19.05 E1.10
N$8
  Top 0.305: E2.10 71.63,16.76 73.15,16.76 E2.11
  Bottom 0.305: E2.12 75.69,16.76 74.17,16.76 E2.11
N$9
  Top 0.305: E2.2 78.23,24.64 76.71,24.64 E2.3
  Bottom 0.305: E2.4 74.17,24.38 75.69,24.38 E2.3
N$10
  Top 0.305: E4.6 41.15,52.32 42.67,52.32 E4.5
  Bottom 0.305: E4.1 52.83,52.32 52.07,51.56 44.45,51.56 43.69,52.32 E4.5
N$11
  Top 0.305: E4.10 43.69,44.7 45.21,44.7 E4.11 46.23,44.7 47.75,44.7 E4.12
N$12
  Top 0.305: E6.10 99.57,44.7 101.09,44.7 E6.11 102.11,44.7 103.63,44.7 E6.12
N$13
  Top 0.305: E6.6 97.03,52.32 98.55,52.32 E6.5
  Bottom 0.305: E6.1 108.71,52.32 107.95,51.56 100.33,51.56 99.57,52.32 E6.5
N$14
  Top 0.305: E5.10 71.63,44.7 73.15,44.7 E5.11 74.17,44.7 75.69,44.7 E5.12
N$15
  Top 0.305: E5.6 69.09,52.32 70.61,52.32 E5.5
  Bottom 0.305: E5.1 80.77,54.36 80.01,55.12 72.39,55.12 71.63,54.36 E5.5
N$16
  Top 0.305: E3.10 99.57,16.76 101.09,16.76 E3.11 102.11,16.76 103.63,16.76 E3.12
N$17
  Top 0.305: E3.6 97.03,24.38 98.55,24.38 E3.5
  Bottom 0.305: E3.1 108.71,24.38 107.95,23.62 100.33,23.62 99.57,24.38 E3.5
N$18
  Bottom 0.305: 113.03,23.88 114.05,24.89 R7.2 | 113.03,23.88 109.73,20.57 108.97,20.57 107.19,18.8 E3.13 | 113.03,23.88 112.01,24.89 C4.1
N$19
  Top 0.305: R17.2 57.91,53.09 56.39,53.09 C9.1
  Bottom 0.305: E4.4 46.23,54.36 46.99,55.12 54.36,55.12 55.63,53.85 C9.1
N$20
  Top 0.305: C10.1 33.53,40.89 35.31,42.67 R19.2 35.81,43.69 35.81,47.5 39.88,47.5 44.45,52.07 44.45,55.12 49.02,55.12 49.53,54.61 49.53,52.07 50.29,51.31 50.29,47.24 50.55,46.99 E4.13
N$21  (via drill 0.71)
  Top 0.305: v63.25,12.95 63.5,13.21 63.5,14.73 R15.2 63.5,15.75 63.5,28.45 64.77,29.72 64.77,31.24 72.9,31.24 73.41,30.73 v73.41,27.69
  Bottom 0.305: v63.25,12.95 62.99,12.7 61.47,12.7 C8.1 | v73.41,27.69 80.01,27.69 81.03,26.67 E2.1
N$22
  Top 0.305: E2.13 78.99,19.05 83.57,23.62 83.57,24.89 C7.1 84.33,25.15 85.85,25.15 R13.2
N$23
  Top 0.305: R14.2 83.57,18.29 83.57,19.81 C7.2 | Q7.2 76.45,9.65 77.47,8.64 77.47,7.37 78.49,6.35 85.85,6.35 85.85,14.99 R13.1
  Bottom 0.305: R14.2 84.07,17.27 85.85,15.49 R13.1
N$24
  Top 0.305: 62.23,6.1 62.99,5.33 R15.1 64.01,5.08 65.79,6.86 65.79,9.65 Q8.2 | 62.23,6.1 61.21,7.11 C8.2 | 62.23,6.1 62.23,13.72 61.21,14.73 R16.2
N$25  (via drill 0.71)
  Top 0.305: C9.2 55.88,47.75 55.88,46.23 R18.2 55.88,45.21 v55.88,43.18 | v38.35,43.18 38.35,42.42 38.1,42.16 38.1,38.61 Q9.2
  Bottom 0.305: v38.35,43.18 v55.88,43.18 57.91,43.18 R17.1
N$26  (via drill 0.71)
  Top 0.305: v33.02,33.02 33.02,35.05 C10.2 32.51,35.81 31.75,36.58 31.75,42.16 32.51,42.93 R20.2 | v48.26,32.77 48.26,37.59 Q10.2
  Bottom 0.305: v33.02,33.02 35.05,33.02 R19.1 36.07,33.02 39.62,33.02 39.88,32.77 41.4,32.77 41.66,33.02 45.47,33.02 45.72,32.77 v48.26,32.77
N$27
  Top 0.305: E5.4 73.41,52.07 69.85,48.51 69.85,40.39 68.83,39.37 65.53,39.37 65.53,40.89 63.75,42.67 R9.2
  Bottom 0.305: C5.1 61.47,40.89 63.25,42.67 R9.2
N$28
  Top 0.305: R9.1 62.99,33.27 61.21,35.05 C5.2 61.47,35.81 64.77,39.12 | 64.77,39.12 65.53,38.35 Q5.2 | 64.77,39.12 61.21,42.67 R10.2
N$29
  Top 0.305: R11.1 86.11,43.69 85.09,44.7 85.09,46.74 84.07,47.75 C6.2 83.57,47.75 82.55,46.74 82.55,37.08 83.57,36.07 R12.2
  Bottom 0.305: Q6.2 76.71,37.85 77.72,36.83 82.3,36.83 83.31,35.81 R12.2
N$30
  Top 0.305: R22.2 88.65,42.67 87.63,41.66 87.63,37.08 88.65,36.07 C11.2 89.15,35.05 90.93,33.27 R21.1 91.69,33.53 91.69,35.56 93.73,37.59 Q11.2
N$31
  Top 0.305: C12.2 111.51,47.75 111.51,46.23 R24.2 112.01,45.21 113.79,43.43 R23.1
  Bottom 0.305: Q12.2 104.65,38.35 105.66,39.37 109.73,39.37 113.28,42.93 113.79,42.93 R23.1
N$32
  Top 0.305: E5.13 78.99,46.99 83.57,51.56 83.57,52.83 C6.1 84.33,53.09 85.85,53.09 R11.2
N$33
  Top 0.305: C11.1 89.41,40.89 91.19,42.67 R21.2 91.69,43.69 91.69,57.15 99.31,57.15 100.33,56.13 100.33,55.63 101.35,54.61 E6.4
N$34
  Bottom 0.305: 112.78,52.32 113.54,53.09 113.79,53.09 R23.2 | 112.78,52.32 107.19,46.74 E6.13 | 112.78,52.32 112.52,52.32 112.01,52.83 C12.1
N$35
  Top 0.305: C3.2 89.15,7.11 90.93,5.33 R5.1 91.69,5.59 93.73,7.62 93.73,9.65 Q3.2
  Bottom 0.305: R6.2 89.15,14.73 93.47,10.41 Q3.2
N$36
  Top 0.305: 111.51,9.91 104.65,9.91 Q4.2 | 111.51,9.91 111.51,8.13 R8.2 | 111.51,9.91 111.51,12.19 114.05,14.73 R7.1 114.05,15.75 114.05,17.78 112.01,19.81 C4.2
P1  (via drill 0.71)
  Top 0.305: v14.99,42.42 13.97,42.42 U$1.P1 | v67.56,51.56 68.58,50.55 68.58,46.99 E5.9
  Bottom 0.305: v14.99,42.42 15.75,43.18 28.45,43.18 28.96,42.67 32,42.67 32.77,41.91 33.27,41.91 33.78,41.4 39.88,41.4 40.39,41.91 40.89,41.91 41.4,41.4 50.04,41.4 51.05,42.42 55.12,42.42 55.37,42.16 57.91,42.16 58.17,41.91 58.67,41.91 59.69,42.93 59.69,43.43 60.96,44.7 63.5,44.7 64.26,43.94 67.82,43.94 68.33,44.45 E5.9 | v67.56,51.56 67.82,51.31 75.18,51.31 75.95,52.07 E5.3
P2  (via drill 0.71)
  Top 0.305: v50.8,39.12 50.8,36.07 Q10.3
  Bottom 0.305: v50.8,39.12 50.04,39.88 41.4,39.88 40.89,39.37 40.39,39.37 40.13,39.62 33.53,39.62 33.27,39.37 32.77,39.37 30.23,41.91 28.7,41.91 28.19,42.42 16.51,42.42 15.49,41.4 13.97,41.4 U$1.P2
R1  (via drill 0.71)
  Top 0.305: v16,36.32 16,43.43 14.99,43.43 13.97,44.45 U$1.R1
  Bottom 0.305: v16,36.32 16.26,36.58 30.48,36.58 32.77,34.29 33.27,34.29 33.53,34.54 37.08,34.54 37.59,34.04 39.62,34.04 40.13,33.53 41.15,33.53 41.4,33.78 45.72,33.78 45.97,33.53 46.99,33.53 49.02,35.56 49.02,36.32 49.78,37.08 63.75,37.08 65.28,35.56 68.07,35.56 Q5.3
R2  (via drill 0.71)
  Top 0.305: v29.46,43.94 29.72,44.2 29.72,50.55 30.48,51.31 30.48,53.34 37.59,60.45 71.12,60.45 71.12,58.67 74.93,54.86 74.93,52.07 75.95,51.05 75.95,48.51 77.47,46.99 77.47,44.45 80.52,41.4 80.52,30.23 80.26,29.97 80.26,28.96 82.3,26.92 92.2,26.92 92.2,16.76 94.74,14.22 94.74,12.95 96.27,11.43 96.77,11.43 101.35,16 105.41,16 105.41,26.67 107.19,28.45 107.19,34.04 107.44,34.29 107.44,34.8 108.2,35.56 108.2,44.2 107.95,44.45 107.95,50.8 107.19,51.56 107.19,52.32 E6.2
  Bottom 0.305: v29.46,43.94 15.49,43.94 15.24,44.2 14.22,44.2 13.97,44.45 U$1.R2
S1  (via drill 0.71)
  Top 0.305: v18.29,39.12 18.29,45.47 16,47.75 13.97,47.75 U$1.S1
  Bottom 0.305: v18.29,39.12 18.54,38.86 32.26,38.86 32.51,38.61 36.07,38.61 37.85,36.83 38.35,36.83 38.61,37.08 47.75,37.08 48.01,36.83 48.51,36.83 49.53,37.85 61.72,37.85 63.5,39.62 66.8,39.62 69.34,37.08 73.91,37.08 75.44,35.56 78.23,35.56 Q6.3
S2  (via drill 0.71)
  Top 0.305: v93.98,41.91 93.98,44.45 E6.8
  Bottom 0.305: v93.98,41.91 88.65,41.91 88.14,41.4 83.06,41.4 80.01,44.45 80.01,46.99 79.5,47.5 61.72,47.5 61.21,46.99 58.17,46.99 57.91,46.74 56.9,46.74 56.64,46.99 55.63,46.99 55.12,47.5 45.72,47.5 43.94,49.28 34.54,49.28 34.04,49.78 14.22,49.78 13.97,49.53 U$1.S2
T2
  Top 0.305: E6.9 96.77,46.99 96.77,50.8 97.54,51.56 103.63,51.56 103.63,52.32 E6.3
  Bottom 0.305: E6.9 96.01,46.74 93.22,49.53 77.98,49.53 77.47,49.02 61.72,49.02 60.96,49.78 44.45,49.78 44.2,50.04 34.8,50.04 34.04,50.8 13.97,50.8 U$1.T2
U2  (via drill 0.71)
  Top 0.305: v97.79,50.29 97.79,42.16 98.04,41.91 98.04,39.12 97.03,38.1 97.03,37.59 96.52,37.08 96.52,36.07 Q11.3
  Bottom 0.305: v97.79,50.29 93.22,50.29 92.96,50.55 77.98,50.55 77.22,49.78 61.98,49.78 61.21,50.55 54.36,50.55 54.1,50.8 35.05,50.8 34.29,51.56 31.5,51.56 29.46,53.59 14.48,53.59 13.97,54.1 U$1.U2
V2
  Bottom 0.305: Q12.3 107.19,35.81 113.28,41.91 114.55,41.91 115.57,42.93 115.57,61.21 21.84,61.21 19.3,58.67 13.97,58.67 U$1.V2
VCC  (via drill 0.71)
  Top 0.305: E3.14 109.22,19.05 v109.22,21.59 108.71,21.84 107.95,22.61 107.95,33.78 108.2,34.04 108.2,34.54 108.97,35.31 108.97,44.45 E6.14 108.71,46.74 108.71,51.05 107.95,51.82 v107.95,55.88 | v71.12,29.46 71.12,28.45 C17.1 71.63,27.69 72.39,26.92 v72.39,19.56 | v52.07,56.13 52.07,52.07 53.34,50.8 53.34,46.99 E4.14 52.83,44.7 52.58,44.45 52.58,28.7 v52.07,28.45 52.07,19.56 52.83,18.8 E1.14 53.34,16.51 53.34,8.38 56.9,4.83 v57.4,4.83 | v81.28,29.46 81.28,44.45 E5.14
  Bottom 0.305: v109.22,21.59 106.17,21.59 104.9,22.86 99.57,22.86 98.81,23.62 98.3,23.62 97.79,24.13 97.79,26.67 98.3,27.18 98.55,27.18 98.81,27.43 C16.1 | v107.95,55.88 99.57,55.88 C13.1 98.55,55.88 96.77,55.88 95.25,57.4 90.68,57.4 89.41,56.13 80.77,56.13 80.52,55.88 71.63,55.88 C14.1 70.61,55.88 68.83,55.88 67.31,57.4 53.09,57.4 52.32,56.64 v52.07,56.13 51.82,55.88 43.69,55.88 C15.1 | U$1.A2 13.97,5.08 27.43,5.08 C19.1 28.45,5.08 57.15,5.08 v57.4,4.83 | 52.07,28.7 52.83,28.7 53.85,29.72 70.87,29.72 v71.12,29.46 71.63,29.72 81.03,29.72 v81.28,29.46 | 52.07,28.7 43.69,28.7 43.43,28.45 C18.1 | v52.07,28.45 52.07,28.7 | v72.39,19.56 80.52,19.56 81.03,19.05 E2.14

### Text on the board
tNames: V1 | V1 | V1 | V1 | V1 | V1 | V1 | V1 | V1 | V1 | V1 | V1 | V1 | V1 | V1 | V1 | V1 | V1 | V1 | V1 | V1 | V1 | V1 | V1 | V1 | V1 | V1 | V1 | V1 | V1 | V1 | V1 | A1 | A1 | A1 | A1 | A1 | A1 | A1 | A1 | A1 | A1 | A1 | A1 | A1 | A1 | A1 | A1 | A1 | A1 | A1 | A1 | A1 | A1 | A1 | A1 | A1 | A1 | A1 | A1 | A1 | A1 | A1 | A1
